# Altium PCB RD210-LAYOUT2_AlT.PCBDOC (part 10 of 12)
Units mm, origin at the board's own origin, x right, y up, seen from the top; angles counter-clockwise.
Board outline 250 x 123 mm, 4 copper layers (TOP, Mid-Layer 1, Mid-Layer 2, BOTTOM), stack 0.711 mm thick; 1043 components, 659 nets, 2786 pads, 1228 vias.
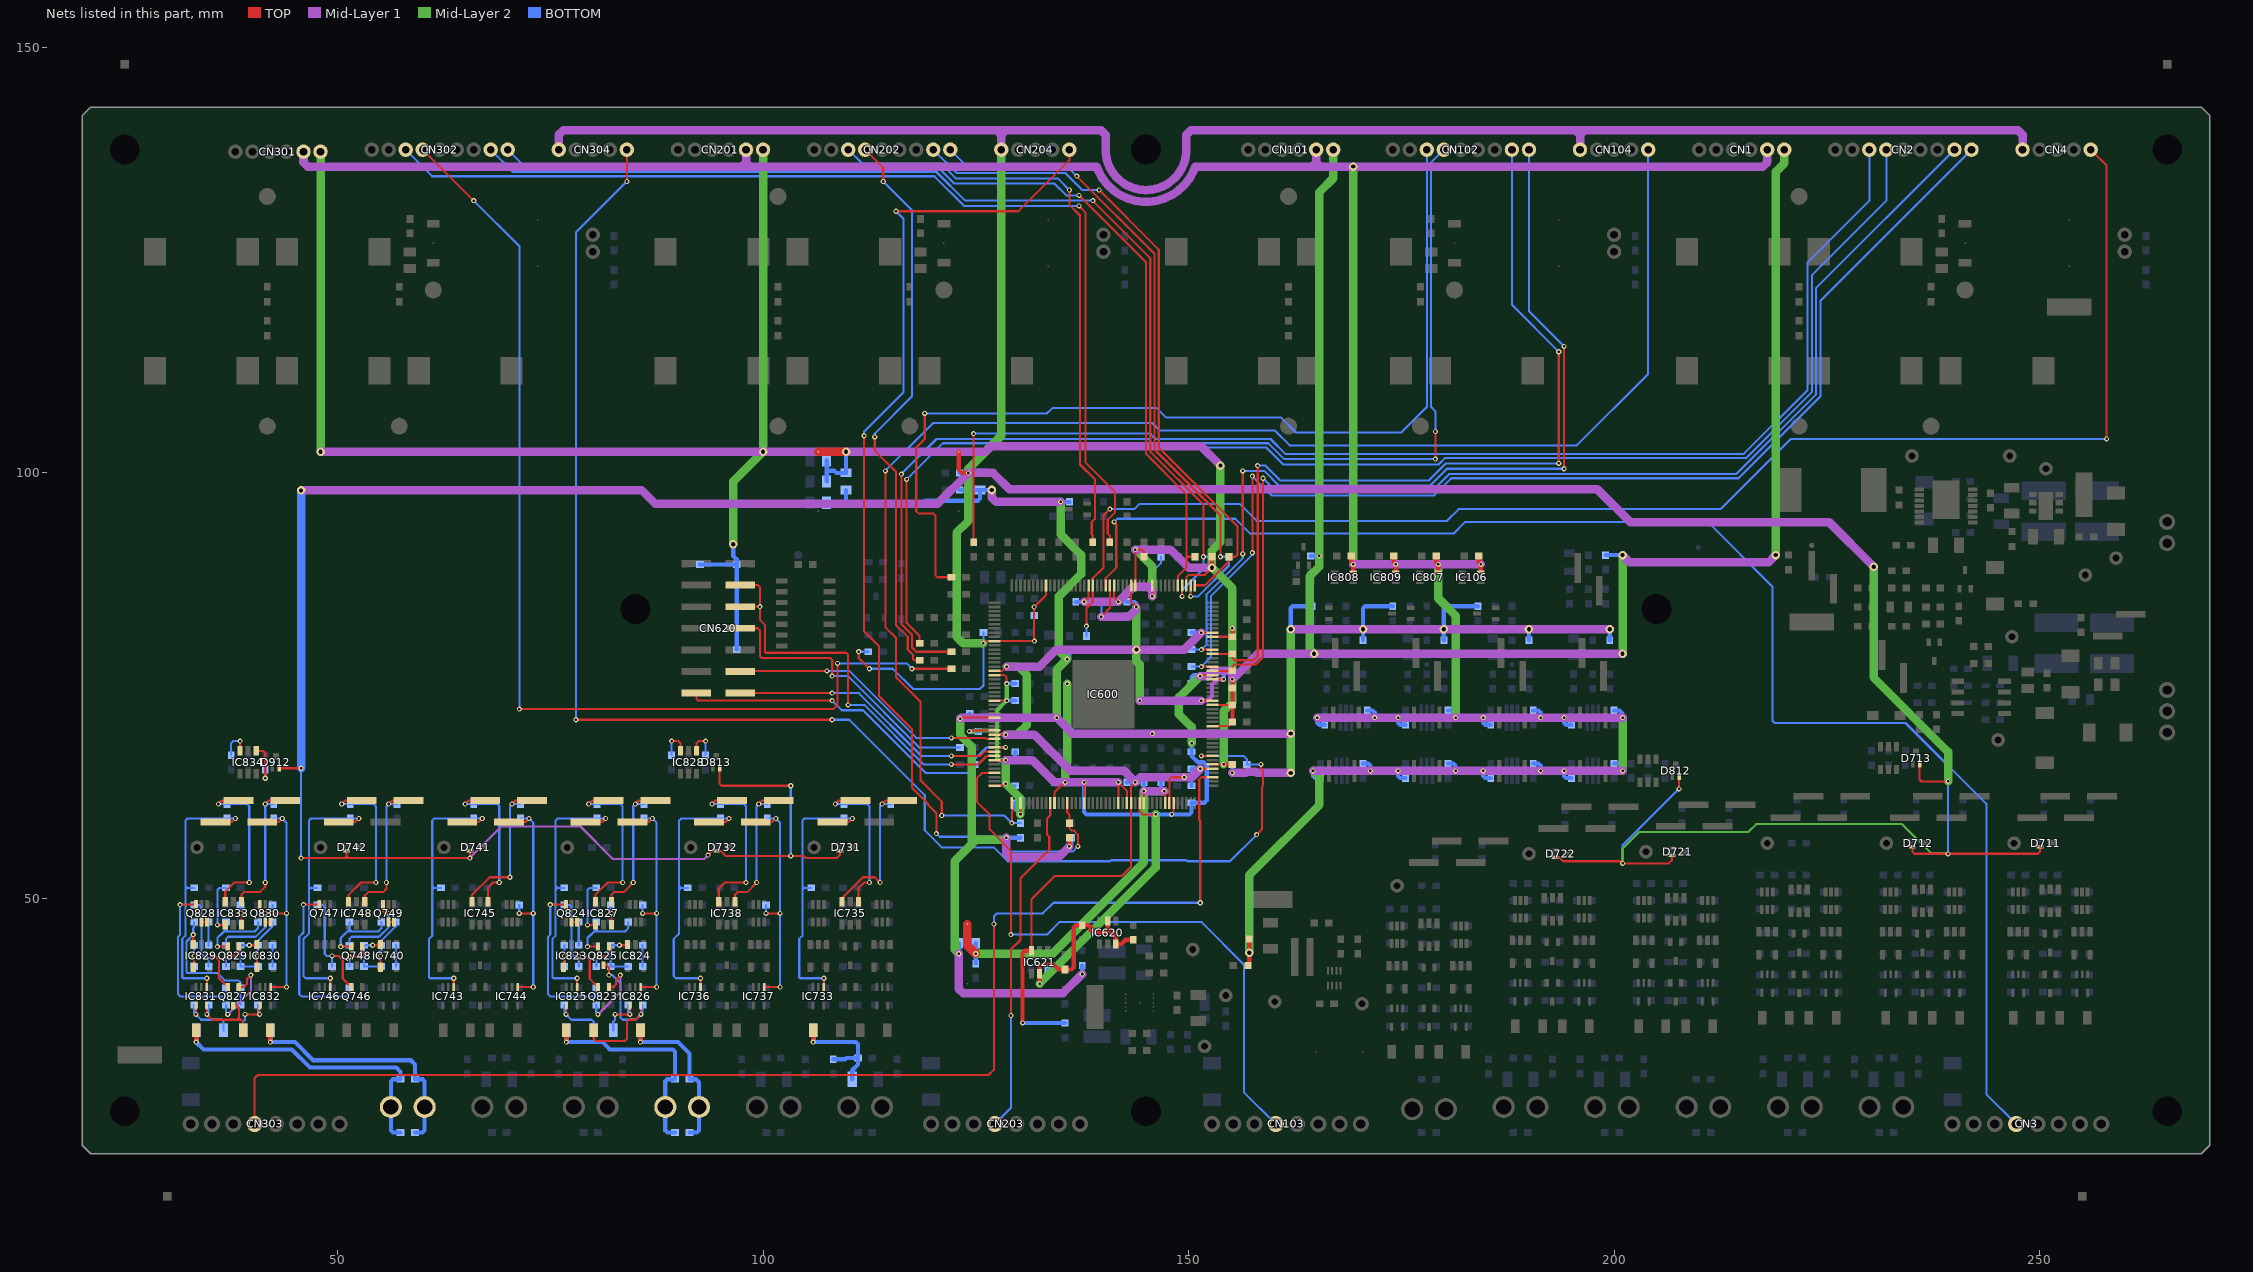
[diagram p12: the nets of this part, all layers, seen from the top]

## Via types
v1: diameter 0.6, hole 0.3, TOP to BOTTOM, 1134 vias
v2: diameter 1, hole 0.5, TOP to BOTTOM, 94 vias

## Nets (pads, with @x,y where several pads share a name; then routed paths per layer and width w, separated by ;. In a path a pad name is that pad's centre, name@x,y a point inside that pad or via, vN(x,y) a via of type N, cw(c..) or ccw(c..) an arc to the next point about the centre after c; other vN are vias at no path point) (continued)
N00400138: Q746.2 R886.1 R888.2 | length 13.7
  TOP w0.25: v1(49.35,43.25) 50.123,43.25 50.607,42.766 50.607,40.593 Q746.2@51.6,39.6
  BOTTOM w0.25: R888.2@47.65,49.25 48.25,49.25 48.5,49 48.5,43.5 48.75,43.25 v1(49.35,43.25) R886.1@49.35,42
N00400139: Q747.6 R882.2 | length 19.4
  TOP w0.25: v1(46,49.275) Q747.6@47.85,49.275
  BOTTOM w0.25: v1(46,49.275) 46,46 45.5,45.5 45.5,38.75 45.75,38.5 51.15,38.5 51.4,38.75 R882.2@51.4,39.5
N00400140: Q749.2 Q749.3 | length 0.6
  TOP w0.25: Q749.2@56,47.225 Q749.3@56.65,47.225
N00400141: Q748.1 R885.1 | length 3.6
  TOP w0.25: v1(51.4,43.147) 52.512,43.147 52.9,43.535 Q748.1@52.9,44.35
  BOTTOM w0.25: R885.1@51.4,42 v1(51.4,43.147)
N00400142: Q749.6 R883.2 | length 9.1
  TOP w0.25: Q749.6@55.35,49.275 55.35,48.5 55.6,48.25 v1(56,48.25)
  BOTTOM w0.25: R883.2@51.4,44.5 51.4,45.25 51.65,45.5 54.875,45.5 56,46.625 v1(56,48.25)
N00400144: Q748.2 R887.1 R889.2 | length 9.8
  TOP w0.25: v1(50.375,44.35) Q748.2@51.6,44.35
  BOTTOM w0.25: v1(50.375,44.35) 50.375,45.35 51.15,46.125 ; R889.2@51.4,47.25 51.4,46.375 ; R887.1@55.15,47.25 55.15,46.5 54.775,46.125 51.65,46.125 ; 51.15,46.125 51.4,46.375 ; 51.15,46.125 51.65,46.125 ; 51.4,46.375 51.65,46.125
N00400145: C781.2 IC740.3 R883.1 R885.2 | length 6.5
  TOP w0.25: v1(54.125,44.5) 54.95,44.5 IC740.3@55.05,44.6
  BOTTOM w0.25: v1(54.125,44.5) R883.1@53.1,44.5 R885.2@53.1,42 C781.2@55.15,42
N00400146: IC740.4 R881.1 R887.2 | length 6.1
  TOP w0.25: IC740.4@55.05,41.9 v1(55.05,43.25)
  BOTTOM w0.25: v1(55.05,43.25) 55.05,43.8 55.15,43.9 R881.1@55.15,44.5 55.15,45.025 56.85,46.725 R887.2@56.85,47.25
N00400149: C781.1 R881.2 | length 2.5
  BOTTOM w0.25: C781.1@56.85,42 R881.2@56.85,44.5
N00400153: C752.2 C753.2 R771.1 R773.2 R778.2 | length 15.5
  TOP w0.5: v1(105.9,33.125) R773.2@105.9,34.5
  BOTTOM w0.5: R771.1@105.9,34.5 v1(105.9,33.125) 110.9,33.125 111.15,32.875 C753.2@111.15,31.25 ; R778.2@108.25,31.1 109.625,31.1 109.775,31.25 C753.2@111.15,31.25 ; C752.2@110.475,28.75 110.475,29.825 111.15,30.5 C753.2@111.15,31.25
N00400154: C931.2 IC824.3 R963.1 R965.2 | length 6.5
  TOP w0.25: v1(83.125,44.5) 83.95,44.5 IC824.3@84.05,44.6
  BOTTOM w0.25: v1(83.125,44.5) R963.1@82.1,44.5 R965.2@82.1,42 C931.2@84.15,42
N00400155: CN929.2 IC738.1 R913.2 | length 16.8
  TOP w0.25: IC738.1@96.7,49.6 96.7,50.45 97,50.75 98.125,50.75 v1(99.25,51.875) ; v1(99.5,61.1) 99.92,61.52 CN929.2@101.85,61.52
  BOTTOM w0.25: v1(99.25,51.875) 99.25,60.85 v1(99.5,61.1) R913.2@100.5,61.1
N00400159: C944.1 IC831.5 Q827.3 R990.2 | length 10.5
  TOP w0.25: IC831.5@34.65,37.4 v1(34.65,36.375) 35.275,35.75 38.15,35.75 ; Q827.3@37.75,37.4 38.178,37.4 38.4,37.178 38.4,36 ; R990.2@38.9,34.5 38.9,35.5 38.65,35.75 ; 38.15,35.75 38.65,35.75 ; 38.15,35.75 38.4,36 ; 38.4,36 38.65,35.75
  BOTTOM w0.25: v1(34.65,36.375) 34.85,36.575 C944.1@34.85,37.5
N00400163: CN927.1 IC736.1 R713.1 R874.1 | length 32.8
  TOP w0.25: IC736.1@92.65,39.6 v1(92.65,40.625) ; CN927.1@93.65,58.98 95.58,58.98 v1(96,59.4)
  BOTTOM w0.25: R874.1@91.15,51.25 90.375,51.25 ; v1(92.65,40.625) 89.75,40.625 89.5,40.875 89.5,45.25 90.125,45.875 90.125,51 ; v1(96,59.4) R713.1@95,59.4 90.375,59.4 90.125,59.15 90.125,51.5 ; 90.125,51 90.375,51.25 ; 90.125,51 90.125,51.5 ; 90.125,51.5 90.375,51.25
N00400164: CN924.2 IC735.1 R703.2 | length 18.8
  TOP w0.25: v1(108.5,61.1) 108.92,61.52 CN924.2@110.85,61.52 ; IC735.1@111.2,49.6 111.2,51.2 111.875,51.875 v1(112.5,51.875)
  BOTTOM w0.25: v1(108.5,61.1) R703.2@109.5,61.1 112.25,61.1 112.5,60.85 v1(112.5,51.875)
N00400165: CN929.1 IC737.1 R875.1 R913.1 | length 28
  TOP w0.25: CN929.1@99.15,58.98 101.08,58.98 v1(101.5,59.4) ; IC737.1@100.15,39.6 v1(102,39.6) ; v1(100.35,48.25) v1(102,48.25)
  BOTTOM w0.25: v1(100.35,48.25) R875.1@100.35,49.25 ; R913.1@100.5,59.4 v1(101.5,59.4) 102,58.9 v1(102,48.25) v1(102,39.6)
N00400166: CN924.1 IC733.1 R703.1 R774.1 | length 32.5
  TOP w0.25: IC733.1@107.15,39.6 v1(107.15,40.625) ; CN924.1@108.15,58.98 110.08,58.98 v1(110.5,59.4)
  BOTTOM w0.25: R774.1@105.65,51.25 104.875,51.25 ; v1(107.15,40.625) 104.375,40.625 104.25,40.75 104.25,45.25 104.625,45.625 104.625,51 ; v1(110.5,59.4) R703.1@109.5,59.4 104.875,59.4 104.625,59.15 104.625,51.5 ; 104.625,51 104.875,51.25 ; 104.625,51 104.625,51.5 ; 104.625,51.5 104.875,51.25
N00400167: C930.1 R960.2 | length 2.7
  BOTTOM w0.25: R960.2@78.35,44.5 C930.1@78.35,47.25
N00400168: C935.1 IC826.5 Q825.3 R973.1 | length 21.5
  TOP w0.25: R973.1@80.1,34.5 80.1,33.5 80.35,33.25 83.75,33.25 84,33.5 84,35.5 84.25,35.75 85.025,35.75 v1(85.65,36.375) IC826.5@85.65,37.4 ; Q825.3@81.25,42.15 81.627,42.15 81.9,41.877 v1(81.9,41)
  BOTTOM w0.25: v1(81.9,41) 82.282,41 83.25,40.031 83.25,36 83.5,35.75 85.025,35.75 v1(85.65,36.375) 85.85,36.575 C935.1@85.85,37.5
N00400169: CN930.2 IC745.1 R704.2 | length 18.8
  TOP w0.25: v1(65,61.1) 65.42,61.52 CN930.2@67.35,61.52 ; IC745.1@67.7,49.6 67.7,51.315 68.26,51.875 v1(69,51.875)
  BOTTOM w0.25: v1(65,61.1) R704.2@66,61.1 68.75,61.1 69,60.85 v1(69,51.875)
N00400171: CN926.2 IC735.3 R903.2 | length 19
  TOP w0.25: IC735.3@109.3,49.6 109.3,50.05 111.75,52.5 113.125,52.5 v1(113.75,51.875) ; v1(114,61.1) 114.42,61.52 CN926.2@116.35,61.52
  BOTTOM w0.25: v1(113.75,51.875) 113.75,60.85 v1(114,61.1) R903.2@115,61.1
N00400173: IC823.4 R960.1 R966.2 | length 3.9
  TOP w0.25: IC823.4@76.55,41.9 76.65,42 v1(76.65,43.25)
  BOTTOM w0.25: R966.2@76.65,42 v1(76.65,43.25) R960.1@76.65,44.5
N00400174: Q825.2 R967.1 R969.2 | length 9.8
  TOP w0.25: v1(79.375,44.35) Q825.2@80.6,44.35
  BOTTOM w0.25: v1(79.375,44.35) 79.375,45.35 80.15,46.125 ; R969.2@80.4,47.25 80.4,46.375 ; R967.1@84.15,47.25 84.15,46.5 83.775,46.125 80.65,46.125 ; 80.15,46.125 80.4,46.375 ; 80.15,46.125 80.65,46.125 ; 80.4,46.375 80.65,46.125
N00400175: CN932.2 IC745.3 R904.2 | length 18.4
  TOP w0.25: IC745.3@65.8,49.6 65.8,50.425 67.875,52.5 v1(70.25,52.5) ; v1(70.5,61.1) 70.92,61.52 CN932.2@72.85,61.52
  BOTTOM w0.25: v1(70.25,52.5) 70.25,60.85 v1(70.5,61.1) R904.2@71.5,61.1
N00400176: IC829.4 R980.1 R986.2 | length 3.9
  TOP w0.25: IC829.4@33.05,41.9 33.15,42 v1(33.15,43.25)
  BOTTOM w0.25: R986.2@33.15,42 v1(33.15,43.25) R980.1@33.15,44.5
N00400177: CN935.2 IC748.1 R914.2 | length 17.2
  TOP w0.25: IC748.1@53.2,49.6 53.2,50.325 53.625,50.75 55.375,50.75 55.75,51.125 v1(55.75,51.875) ; v1(56,61.1) 56.42,61.52 CN935.2@58.35,61.52
  BOTTOM w0.25: v1(55.75,51.875) 55.75,60.85 v1(56,61.1) R914.2@57,61.1
N00400178: CN932.1 IC744.1 R795.1 R904.1 | length 28
  TOP w0.25: CN932.1@70.15,58.98 72.08,58.98 v1(72.5,59.4) ; IC744.1@71.15,39.6 v1(73,39.6) ; v1(71.35,48.25) v1(73,48.25)
  BOTTOM w0.25: v1(71.35,48.25) R795.1@71.35,49.25 ; R904.1@71.5,59.4 v1(72.5,59.4) 73,58.9 v1(73,48.25) v1(73,39.6)
N00400179: CN933.1 IC746.1 R714.1 R894.1 | length 32.8
  TOP w0.25: IC746.1@49.15,39.6 v1(49.15,40.625) ; CN933.1@50.15,58.98 52.08,58.98 v1(52.5,59.4)
  BOTTOM w0.25: R894.1@47.65,51.25 46.875,51.25 ; v1(49.15,40.625) 46.25,40.625 46,40.875 46,45.25 46.625,45.875 46.625,51 ; v1(52.5,59.4) R714.1@51.5,59.4 46.875,59.4 46.625,59.15 46.625,51.5 ; 46.625,51 46.625,51.5 ; 46.625,51 46.875,51.25 ; 46.625,51.5 46.875,51.25
N00400180: CN930.1 IC743.1 R704.1 R794.1 | length 32.5
  TOP w0.25: IC743.1@63.65,39.6 v1(63.65,40.625) ; CN930.1@64.65,58.98 66.58,58.98 v1(67,59.4)
  BOTTOM w0.25: R794.1@62.15,51.25 61.375,51.25 ; v1(63.65,40.625) 60.875,40.625 60.75,40.75 60.75,45.25 61.125,45.625 61.125,51 ; v1(67,59.4) R704.1@66,59.4 61.375,59.4 61.125,59.15 61.125,51.5 ; 61.125,51 61.125,51.5 ; 61.125,51 61.375,51.25 ; 61.125,51.5 61.375,51.25
N00400182: CN937.1 IC825.1 R718.1 R974.1 | length 32.5
  TOP w0.25: IC825.1@78.15,39.6 v1(78.15,40.625) ; CN937.1@79.15,58.98 81.08,58.98 v1(81.5,59.4)
  BOTTOM w0.25: R974.1@76.65,51.25 75.875,51.25 ; v1(78.15,40.625) 75.375,40.625 75.25,40.75 75.25,45.25 75.625,45.625 75.625,51 ; v1(81.5,59.4) R718.1@80.5,59.4 75.875,59.4 75.625,59.15 75.625,51.5 ; 75.625,51 75.875,51.25 ; 75.625,51 75.625,51.5 ; 75.625,51.5 75.875,51.25
N00400183: C941.2 IC830.3 R983.1 R985.2 | length 6.5
  TOP w0.25: v1(39.625,44.5) 40.45,44.5 IC830.3@40.55,44.6
  BOTTOM w0.25: v1(39.625,44.5) R983.1@38.6,44.5 R985.2@38.6,42 C941.2@40.65,42
N00400184: C945.2 IC832.4 R992.2 | length 5.9
  TOP w0.25: v1(39.125,36.375) v1(40.85,36.375) IC832.4@40.85,37.4
  BOTTOM w0.25: R992.2@38.9,34.5 38.9,35.525 39.125,35.75 v1(39.125,36.375) ; C945.2@40.65,37.5 40.65,36.575 v1(40.85,36.375)
N00400185: CN939.2 IC827.1 R918.2 | length 16.8
  TOP w0.25: IC827.1@82.2,49.6 82.2,50.45 82.5,50.75 83.625,50.75 v1(84.75,51.875) ; v1(85,61.1) 85.42,61.52 CN939.2@87.35,61.52
  BOTTOM w0.25: v1(84.75,51.875) 84.75,60.85 v1(85,61.1) R918.2@86,61.1
N00400186: CN937.2 IC827.3 R718.2 | length 20.2
  TOP w0.25: v1(79.5,61.1) 79.92,61.52 CN937.2@81.85,61.52 ; IC827.3@80.3,49.6 80.3,50.425 81.75,51.875 v1(83.5,51.875)
  BOTTOM w0.25: v1(79.5,61.1) R718.2@80.5,61.1 83.25,61.1 83.5,60.85 v1(83.5,51.875)
N00400187: IC833.6 R996.1 | length 2.4
  TOP w0.25: IC833.6@38.7,46.9 v1(38.7,48.25)
  BOTTOM w0.25: R996.1@38.6,49.25 38.6,48.725 38.7,48.625 v1(38.7,48.25)
N00400191: CN943.1 IC832.1 R919.1 R995.1 | length 28
  TOP w0.25: CN943.1@41.15,58.98 43.08,58.98 v1(43.5,59.4) ; IC832.1@42.15,39.6 v1(44,39.6) ; v1(42.35,48.25) v1(44,48.25)
  BOTTOM w0.25: v1(42.35,48.25) R995.1@42.35,49.25 ; R919.1@42.5,59.4 v1(43.5,59.4) 44,58.9 v1(44,48.25) v1(44,39.6)
N00400192: C935.2 IC826.4 R972.2 | length 5.9
  TOP w0.25: v1(82.625,36.375) v1(84.35,36.375) IC826.4@84.35,37.4
  BOTTOM w0.25: R972.2@82.4,34.5 82.4,35.525 82.625,35.75 v1(82.625,36.375) ; C935.2@84.15,37.5 84.15,36.575 v1(84.35,36.375)
N00400193: CN939.1 IC826.1 R918.1 R975.1 | length 28
  TOP w0.25: CN939.1@84.65,58.98 86.58,58.98 v1(87,59.4) ; IC826.1@85.65,39.6 v1(87.5,39.6) ; v1(85.85,48.25) v1(87.5,48.25)
  BOTTOM w0.25: v1(85.85,48.25) R975.1@85.85,49.25 ; R918.1@86,59.4 v1(87,59.4) 87.5,58.9 v1(87.5,48.25) v1(87.5,39.6)
N00400194: C933.1 CN936.1 R970.1 R972.1 R979.2 | length 20.2
  TOP w0.5: v1(85.6,33.125) R970.1@85.6,34.5
  BOTTOM w0.5: R972.1@85.6,34.5 v1(85.6,33.125) 90,33.125 91.35,31.775 R979.2@91.35,28.75 92.125,28.75 92.48,28.395 92.48,22.75 92.23,22.5 C933.1@91.35,22.5
N00400202: C933.2 CN936.2 R971.1 R973.2 R979.1 | length 27.4
  TOP w0.5: v1(76.9,33.125) R973.2@76.9,34.5
  BOTTOM w0.5: R971.1@76.9,34.5 v1(76.9,33.125) 81.125,33.125 82,32.25 89.4,32.25 89.65,32 R979.1@89.65,28.75 88.75,28.75 88.52,28.52 CN936.2@88.52,25.5 88.52,22.75 88.77,22.5 C933.2@89.65,22.5
N00400204: C934.2 IC825.4 R971.2 | length 6.8
  TOP w0.25: v1(76.85,36.375) IC825.4@76.85,37.4
  BOTTOM w0.25: C934.2@76.65,37.5 76.65,36.575 v1(76.85,36.375) 77.475,35.75 79.85,35.75 80.1,35.5 R971.2@80.1,34.5
N00400205: Q830.6 R983.2 | length 9.1
  TOP w0.25: Q830.6@40.85,49.275 40.85,48.5 41.1,48.25 v1(41.5,48.25)
  BOTTOM w0.25: R983.2@36.9,44.5 36.9,45.25 37.15,45.5 40.375,45.5 41.5,46.625 v1(41.5,48.25)
N00400206: Q830.2 Q830.3 | length 0.6
  TOP w0.25: Q830.2@41.5,47.225 Q830.3@42.15,47.225
N00400208: IC827.6 R976.1 | length 2.4
  TOP w0.25: IC827.6@82.2,46.9 v1(82.2,48.25)
  BOTTOM w0.25: R976.1@82.1,49.25 82.1,48.725 82.2,48.625 v1(82.2,48.25)
N00400211: C940.1 R980.2 | length 2.7
  BOTTOM w0.25: R980.2@34.85,44.5 C940.1@34.85,47.25
N00400212: Q827.2 R986.1 R988.2 | length 13.7
  TOP w0.25: v1(34.85,43.25) 35.59,43.25 36.074,42.766 36.074,40.625 Q827.2@37.1,39.6
  BOTTOM w0.25: R988.2@33.15,49.25 33.75,49.25 34,49 34,43.5 34.25,43.25 v1(34.85,43.25) R986.1@34.85,42
N00400213: C940.2 IC829.3 R982.1 R984.2 | length 16.9
  TOP w0.25: IC829.3@33.05,44.6 v1(33.05,45.75)
  BOTTOM w0.25: C940.2@33.15,47.25 33.15,46.6 33.05,46.5 v1(33.05,45.75) 32.25,44.95 32.25,41.375 32.375,41.25 35.875,41.25 36.75,40.375 38.35,40.375 38.6,40.125 R982.1@38.6,39.5 R984.2@38.6,37.5
N00400214: C943.2 CN940.2 R991.1 R993.2 R999.1 | length 37.3
  TOP w0.5: v1(33.4,33.125) R993.2@33.4,34.5
  BOTTOM w0.5: R991.1@33.4,34.5 v1(33.4,33.125) 33.4,33.1 34.25,32.25 44.625,32.25 46.75,30.125 56.9,30.125 57.4,29.625 R999.1@57.4,28.75 56.52,28.75 56.27,28.5 CN940.2@56.27,25.5 56.27,22.75 56.52,22.5 C943.2@57.4,22.5
N00400216: Q828.2 Q828.3 | length 0.7
  TOP w0.25: Q828.2@34,47.225 Q828.3@34.65,47.225
N00400217: Q827.1 R984.1 | length 9.3
  TOP w0.25: Q827.1@38.4,39.6 38.987,39.6 39.359,39.972 39.359,40.543 v1(39.812,40.997)
  Mid-Layer 1 w0.25: v1(37.1,36.375) 39.812,39.087 v1(39.812,40.997)
  BOTTOM w0.25: R984.1@36.9,37.5 36.9,36.575 v1(37.1,36.375)
N00400220: Q828.6 R982.2 | length 19.1
  TOP w0.25: v1(31.5,49.275) Q828.6@33.35,49.275
  BOTTOM w0.25: v1(31.5,49.275) 31.5,45.75 31.25,45.5 31.25,38.75 31.5,38.5 36.65,38.5 36.9,38.75 R982.2@36.9,39.5
N00400221: CN941.2 IC833.3 R719.2 | length 19.7
  TOP w0.25: v1(36,61.1) 36.42,61.52 CN941.2@38.35,61.52 ; IC833.3@36.8,49.6 36.8,50.8 37.875,51.875 v1(39.625,51.875)
  BOTTOM w0.25: v1(36,61.1) R719.2@37,61.1 39.375,61.1 39.625,60.85 v1(39.625,51.875)
N00400224: IC833.4 R997.1 | length 6.2
  TOP w0.25: v1(35.875,46.9) IC833.4@36.8,46.9
  BOTTOM w0.25: v1(35.875,46.9) 35.875,51 36.125,51.25 R997.1@36.9,51.25
N00400225: CN943.2 IC833.1 R919.2 | length 17.3
  TOP w0.25: IC833.1@38.7,49.6 38.7,50.45 39,50.75 40.875,50.75 41.5,51.375 v1(41.5,51.875) ; v1(41.5,61.1) 41.92,61.52 CN943.2@43.85,61.52
  BOTTOM w0.25: v1(41.5,51.875) v1(41.5,61.1) R919.2@42.5,61.1
N00400226: IC827.4 R977.1 | length 6.2
  TOP w0.25: v1(79.375,46.9) IC827.4@80.3,46.9
  BOTTOM w0.25: v1(79.375,46.9) 79.375,51 79.625,51.25 R977.1@80.4,51.25
N00400228: IC834.6 R709.1 | length 3.7
  TOP w0.25: IC834.6@38.55,67.35 v1(38.55,68.5)
  BOTTOM w0.25: R709.1@37.5,66.85 37.5,68.25 37.75,68.5 v1(38.55,68.5)
N00400229: Q829.1 R985.1 | length 3.7
  TOP w0.25: v1(36.9,43.274) 38.098,43.274 38.4,43.576 Q829.1@38.4,44.35
  BOTTOM w0.25: R985.1@36.9,42 v1(36.9,43.274)
N00400230: Q829.2 R987.1 R989.2 | length 9.8
  TOP w0.25: v1(35.875,44.35) Q829.2@37.1,44.35
  BOTTOM w0.25: v1(35.875,44.35) 35.875,45.35 36.65,46.125 ; R989.2@36.9,47.25 36.9,46.375 ; R987.1@40.65,47.25 40.65,46.5 40.275,46.125 37.15,46.125 ; 36.65,46.125 36.9,46.375 ; 36.65,46.125 37.15,46.125 ; 36.9,46.375 37.15,46.125
N00400231: IC834.4 R909.1 | length 5.2
  TOP w0.25: IC834.4@40.45,67.35 41.25,67.35 41.5,67.1 v1(41.5,64.125)
  BOTTOM w0.25: v1(41.5,64.125) R909.1@41.5,65.15
N00400232: IC830.4 R981.1 R987.2 | length 6.1
  TOP w0.25: IC830.4@40.55,41.9 v1(40.55,43.25)
  BOTTOM w0.25: v1(40.55,43.25) 40.55,43.8 40.65,43.9 R981.1@40.65,44.5 40.65,45.025 42.35,46.725 R987.2@42.35,47.25
N00400233: C941.1 R981.2 | length 2.5
  BOTTOM w0.25: C941.1@42.35,42 R981.2@42.35,44.5
N00400234: Q823.1 R964.1 | length 9.2
  TOP w0.25: Q823.1@81.9,39.6 82.421,39.6 82.738,39.917 82.738,40.48 v1(83.246,40.988)
  Mid-Layer 1 w0.25: v1(80.6,36.375) 83.246,39.021 v1(83.246,40.988)
  BOTTOM w0.25: R964.1@80.4,37.5 80.4,36.575 v1(80.6,36.375)
N00400235: Q823.2 R966.1 R968.2 | length 13.7
  TOP w0.25: v1(78.35,43.25) 79.151,43.25 79.635,42.766 79.635,40.565 Q823.2@80.6,39.6
  BOTTOM w0.25: R968.2@76.65,49.25 77.25,49.25 77.5,49 77.5,43.5 77.75,43.25 v1(78.35,43.25) R966.1@78.35,42
N00400236: Q824.6 R962.2 | length 19.1
  TOP w0.25: v1(75,49.275) Q824.6@76.85,49.275
  BOTTOM w0.25: v1(75,49.275) 75,45.75 74.75,45.5 74.75,38.75 75,38.5 80.15,38.5 80.4,38.75 R962.2@80.4,39.5
N00400237: C931.1 R961.2 | length 2.5
  BOTTOM w0.25: C931.1@85.85,42 R961.2@85.85,44.5
N00400239: Q824.2 Q824.3 | length 0.6
  TOP w0.25: Q824.2@77.5,47.225 Q824.3@78.15,47.225
N00400242: Q825.1 R965.1 | length 3.7
  TOP w0.25: v1(80.4,43.21) 81.595,43.21 81.9,43.515 Q825.1@81.9,44.35
  BOTTOM w0.25: R965.1@80.4,42 v1(80.4,43.21)
N00400243: CN941.1 IC831.1 R719.1 R994.1 | length 32.5
  TOP w0.25: IC831.1@34.65,39.6 v1(34.65,40.625) ; CN941.1@35.65,58.98 37.58,58.98 v1(38,59.4)
  BOTTOM w0.25: R994.1@33.15,51.25 32.375,51.25 ; v1(34.65,40.625) 31.875,40.625 31.75,40.75 31.75,45.25 32.125,45.625 32.125,51 ; v1(38,59.4) R719.1@37,59.4 32.375,59.4 32.125,59.15 32.125,51.5 ; 32.125,51 32.125,51.5 ; 32.125,51 32.375,51.25 ; 32.125,51.5 32.375,51.25
N00400244: C944.2 IC831.4 R991.2 | length 6.8
  TOP w0.25: v1(33.35,36.375) IC831.4@33.35,37.4
  BOTTOM w0.25: C944.2@33.15,37.5 33.15,36.575 v1(33.35,36.375) 33.975,35.75 36.35,35.75 36.6,35.5 R991.2@36.6,34.5
N00400246: CN927.2 IC738.3 R713.2 | length 20.7
  TOP w0.25: v1(94,61.1) 94.42,61.52 CN927.2@96.35,61.52 ; IC738.3@94.8,49.6 94.8,51.175 95.5,51.875 v1(98,51.875)
  BOTTOM w0.25: v1(94,61.1) R713.2@95,61.1 97.75,61.1 98,60.85 v1(98,51.875)
N00400247: C943.1 CN940.1 R990.1 R992.1 R999.2 | length 30.8
  TOP w0.5: v1(42.1,33.125) R990.1@42.1,34.5
  BOTTOM w0.5: R992.1@42.1,34.5 v1(42.1,33.125) 45,33.125 47.125,31 58.6,31 59.1,30.5 R999.2@59.1,28.75 59.98,28.75 60.23,28.5 60.23,22.75 59.98,22.5 C943.1@59.1,22.5
N00400253: IC828.6 R708.1 | length 3.7
  TOP w0.25: v1(89.25,68.5) 90.05,68.5 90.3,68.25 IC828.6@90.3,67.35
  BOTTOM w0.25: R708.1@89.25,66.85 v1(89.25,68.5)
N00400256: IC828.4 R908.1 | length 3.7
  TOP w0.25: IC828.4@92.2,67.35 92.2,68.25 92.45,68.5 v1(93.25,68.5)
  BOTTOM w0.25: R908.1@93.25,66.85 v1(93.25,68.5)
N00400257: CN933.2 IC748.3 R714.2 | length 20.2
  TOP w0.25: v1(50.5,61.1) 50.92,61.52 CN933.2@52.85,61.52 ; IC748.3@51.3,49.6 51.3,50.425 52.75,51.875 v1(54.5,51.875)
  BOTTOM w0.25: v1(50.5,61.1) R714.2@51.5,61.1 54.25,61.1 54.5,60.85 v1(54.5,51.875)
PowrGood_0-1: CN4.1 IC600.25 R514.2 | length 173
  TOP w0.25: v1(138,82) 138,84.125 138.75,84.875 IC600.25@138.75,86.8 138.75,87.625 140,88.875 140,95 v1(140.75,95.75) ; CN4.1@256,138 257.875,136.125 v1(257.875,104)
  BOTTOM w0.25: R514.2@138,80.85 v1(138,82) ; v1(140.75,95.75) 143.625,95.75 144.25,96.375 156,96.375 158,94.375 180.375,94.375 181.75,95.75 212.5,95.75 220.75,104 v1(257.875,104)
PowrGood_0-2: CN104.1 IC600.89 R524.1 | length 178.1
  TOP w0.25: v1(114.375,100.25) 114.375,81.875 115.625,80.625 115.625,76 118.5,73.125 118.5,63.875 121,61.375 v1(121,59.75) ; v1(129.25,58.85) IC600.89@129.25,61.2
  BOTTOM w0.25: v1(114.375,100.25) 120,105.875 145.75,105.875 146.625,105 160.125,105 161.875,103.25 195.625,103.25 204,111.625 CN104.1@204,138 ; v1(121,59.75) 128.35,59.75 v1(129.25,58.85) R524.1@130.25,58.85
PowrGood_0-3: CN204.1 IC600.102 R534.1 | length 126.5
  TOP w0.25: v1(111.875,104.375) 111.875,81.375 113.625,79.625 113.625,73.75 117.5,69.875 117.5,63 119.375,61.125 119.375,61 120.375,60 v1(120.375,57.625) ; v1(115.625,130.75) 130,130.75 136,136.75 CN204.1@136,138 ; IC600.102@135.75,61.2 135.75,60.125 136,59.875 R534.1@136,58.85 136,58.25 136.25,58 136.5,58 137,57.5 v1(137,56.125)
  BOTTOM w0.25: v1(111.875,104.375) 111.875,104.875 116.5,109.5 116.5,129.875 v1(115.625,130.75) ; v1(120.375,57.625) 120.75,57.25 127.375,57.25 129.125,55.5 136.375,55.5 v1(137,56.125)
PowrGood_0-4: CN304.1 IC600.140 R544.2 | length 177.9
  TOP w0.25: v1(78,71) v1(108.125,71) ; v1(84,134.25) CN304.1@84,138 ; v1(151.5,66.75) IC600.140@152.8,66.75 ; v1(158,57.5) 158.625,58.125 158.625,63.125 158.75,63.25 158.75,65 158.5,65.25 v1(158.5,65.75)
  BOTTOM w0.25: v1(78,71) 78,128.25 v1(84,134.25) ; v1(108.125,71) 110.125,71 119,62.125 119,58 121,56 127.125,56 128.75,54.375 140.75,54.375 140.875,54.5 149.75,54.5 149.875,54.375 154.875,54.375 v1(158,57.5) ; v1(151.5,66.75) 156.475,66.75 156.85,66.375 R544.2@156.85,65.75 v1(158.5,65.75)
PWM_H_0-1: CN2.2 IC600.160 R551.2 | length 133.7
  TOP w0.25: IC600.160@152.8,76.75 R551.2@155.15,76.75 155.15,77.25 155.4,77.5 157.875,77.5 158.75,78.375 v1(158.75,99.375)
  BOTTOM w0.25: v1(158.75,99.375) 160.25,97.875 178.625,97.875 180.625,99.875 214.375,99.875 223.75,109.25 223.75,121.75 CN2.2@240,138
PWM_H_0-2: CN102.2 IC600.164 R552.2 | length 104.6
  TOP w0.25: IC600.164@152.8,78.75 R552.2@155.15,78.75 155.15,78.25 155.4,78 157.625,78 158.125,78.5 v1(158.125,100.875) ; v1(193.5,101.125) v1(193.5,114.25)
  BOTTOM w0.25: v1(158.125,100.875) 159,100.875 160.75,99.125 178.25,99.125 180.25,101.125 v1(193.5,101.125) ; CN102.2@188,138 188,119.75 v1(193.5,114.25)
PWM_H_0-3: CN202.2 IC600.1 R553.2 | length 77.8
  TOP w0.25: v1(139.5,133.25) 146.5,126.25 146.5,103 155.75,93.75 155.75,90.4 155.5,90.15 R553.2@154.75,90.15 154.75,89.625 151.925,86.8 IC600.1@150.75,86.8
  BOTTOM w0.25: CN202.2@120,138 122.75,135.25 135.5,135.25 137.5,133.25 v1(139.5,133.25)
PWM_H_0-4: CN302.2 IC600.4 R554.2 | length 128.5
  TOP w0.25: v1(138.75,132) 145.5,125.25 145.5,102.5 151.75,96.25 v1(151.75,90.15) ; v1(149.25,85.5) IC600.4@149.25,86.8
  BOTTOM w0.25: CN302.2@68,138 70.625,135.375 120.375,135.375 123.75,132 v1(138.75,132) ; v1(149.25,85.5) 149.25,86.25 151.75,88.75 v1(151.75,90.15) R554.2@152.75,90.15
PWM_L_0-1: CN2.1 IC600.161 R556.2 | length 136.2
  TOP w0.25: v1(151.5,77.25) IC600.161@152.8,77.25 ; v1(157.5,90.625) v1(157.5,99.625)
  BOTTOM w0.25: R556.2@150.35,77.25 v1(151.5,77.25) 152.625,78.375 152.625,85.5 157.5,90.375 v1(157.5,90.625) ; v1(157.5,99.625) 159.75,97.375 178.875,97.375 180.875,99.375 214.625,99.375 224.25,109 224.25,120.25 CN2.1@242,138
PWM_L_0-2: CN102.1 IC600.165 R557.2 | length 104
  TOP w0.25: v1(151.5,79.25) IC600.165@152.8,79.25 ; v1(156.375,90.5) v1(156.375,100.25) ; v1(194.125,100.5) v1(194.125,114.875)
  BOTTOM w0.25: R557.2@150.35,79.25 v1(151.5,79.25) 152.125,79.875 152.125,85.75 156.375,90 v1(156.375,90.5) ; v1(156.375,100.25) 158.875,100.25 160.625,98.5 178.375,98.5 180.375,100.5 v1(194.125,100.5) ; CN102.1@190,138 190,119 v1(194.125,114.875)
PWM_L_0-3: CN202.1 IC600.2 R558.2 | length 77.2
  TOP w0.25: v1(136.875,134.875) 146,125.75 146,102.75 153.75,95 v1(153.75,90.15) ; v1(150.25,85.5) IC600.2@150.25,86.8
  BOTTOM w0.25: CN202.1@122,138 124.125,135.875 135.875,135.875 v1(136.875,134.875) ; v1(150.25,85.5) 151.125,85.5 154.75,89.125 R558.2@154.75,90.15 v1(153.75,90.15)
PWM_L_0-4: CN302.1 IC600.5 R559.2 | length 122.3
  TOP w0.25: v1(137.125,132.625) 145,124.75 145,102.25 149.75,97.5 149.75,90.4 ; IC600.5@148.75,86.8 148.75,87.875 149.75,88.875 149.75,89.9 ; R559.2@150.75,90.15 150,90.15 ; 149.75,89.9 150,90.15 ; 149.75,89.9 149.75,90.4 ; 149.75,90.4 150,90.15
  BOTTOM w0.25: CN302.1@70,138 72.125,135.875 120.625,135.875 122.5,134 134.25,134 135.625,132.625 v1(137.125,132.625)
STBY_0-1: CN3.5 IC600.22 | length 174
  TOP w0.25: IC600.22@140.25,86.8 140.25,87.625 141.5,88.875 141.5,94 v1(141.25,94.25)
  BOTTOM w0.25: v1(141.25,94.25) 141.625,94.625 155.5,94.625 157.25,92.875 181.125,92.875 182.5,94.25 211,94.25 218.625,86.625 218.625,70.875 218.875,70.625 234.25,70.625 243.75,61.125 243.75,27 CN3.5@247.25,23.5
STBY_0-2: CN103.5 IC600.85 | length 72.7
  TOP w0.25: IC600.85@127.2,64.75 125.75,64.75 125.125,64.125 125.125,61.375 126.625,59.875 126.625,58.125 129.125,55.625 v1(129.125,45.75)
  BOTTOM w0.25: v1(129.125,45.75) 133.375,45.75 134.875,47.25 151.5,47.25 156.5,42.25 156.5,27.25 CN103.5@160.25,23.5
STBY_0-3: CN203.5 IC600.98 | length 40.6
  TOP w0.25: v1(129.125,36.25) 129.125,44 130.25,45.125 130.25,52.375 133.625,55.75 133.625,57.25 133.375,57.5 133.375,59.375 133.75,59.75 IC600.98@133.75,61.2
  BOTTOM w0.25: CN203.5@127.25,23.5 129.125,25.375 v1(129.125,36.25)
STBY_0-4: CN303.5 IC600.135 | length 151.8
  TOP w0.25: CN303.5@40.25,23.5 40.25,28.875 40.625,29.25 126.5,29.25 127.125,29.875 v1(127.125,47) ; v1(151.375,49.5) 151.375,59.125 151.25,59.25 151.25,64 151.5,64.25 IC600.135@152.8,64.25
  BOTTOM w0.25: v1(127.125,47) 127.125,47.875 127.5,48.25 132.875,48.25 134.125,49.5 v1(151.375,49.5)
TCK: CN620.9 CN620.11 IC600.81 | length 48.8
  TOP w0.25: CN620.9@97.34,84.29 v1(99.625,84.29) ; CN620.11@97.34,86.83 99.375,86.83 99.625,86.58 v1(99.625,84.29) ; v1(110,72.75) 110,78.625 109.75,78.875 100.375,78.875 100.25,79 100.25,82.125 99.625,82.75 v1(99.625,84.29) ; v1(122.125,65.75) 125.25,65.75 126.25,66.75 IC600.81@127.2,66.75
  BOTTOM w0.25: v1(110,72.75) 111.875,72.75 118.875,65.75 v1(122.125,65.75)
TDI: CN620.3 IC600.77 | length 33.2
  TOP w0.25: CN620.3@97.34,76.67 97.42,76.75 v1(107.5,76.75) ; v1(122.125,68.875) 126.125,68.875 126.25,68.75 IC600.77@127.2,68.75
  BOTTOM w0.25: v1(107.5,76.75) 110.125,76.75 118,68.875 v1(122.125,68.875)
TDO: CN620.7 R659.2 | length 34.5
  TOP w0.25: CN620.7@97.34,81.75 99.375,81.75 99.625,81.5 99.625,78.5 99.875,78.25 107.875,78.25 108.125,78 v1(108.125,76.125)
  BOTTOM w0.25: v1(108.125,76.125) 110,76.125 118.375,67.75 R659.2@123.15,67.75
TMS: CN620.1 IC600.80 | length 33.1
  TOP w0.25: CN620.1@97.34,74.13 v1(108.125,74.13) ; v1(122.125,66.75) 125.5,66.75 126,67.25 IC600.80@127.2,67.25
  BOTTOM w0.25: v1(108.125,74.13) 111.245,74.13 118.625,66.75 v1(122.125,66.75)
TRST_N: CN620.2 IC600.79 R669.2 | length 43.9
  TOP w0.25: CN620.2@92.16,74.13 92.16,73.5 92.41,73.25 v1(108.125,73.25) ; IC600.79@127.2,67.75 v1(128.5,67.75)
  BOTTOM w0.25: v1(108.125,73.25) 109.25,72.125 111.75,72.125 119.125,64.75 124.6,64.75 124.85,65 R669.2@124.85,65.75 124.85,66.35 126.25,67.75 v1(128.5,67.75)
V_B0-1: CN2.7 R512.2 | length 146.1
  TOP w0.25: R512.2@124.75,91.85 v1(124.75,104.625)
  BOTTOM w0.25: v1(124.75,104.625) 145.5,104.625 146.125,104 159.625,104 161.375,102.25 215.25,102.25 222.75,109.75 222.75,124.75 230,132 CN2.7@230,138
V_B0-2: CN102.7 R522.1 | length 115.3
  TOP w0.25: v1(119,107) 119,104 118,103 118,95.5 118.25,95.25 120,95.25 120.25,95 120.25,88 120.5,87.75 R522.1@122.15,87.75
  BOTTOM w0.25: v1(119,107) 133.375,107 134,107.625 146.25,107.625 147.375,106.5 160.875,106.5 162.625,104.75 175,104.75 178,107.75 CN102.7@178,138
V_B0-3: CN202.7 R532.1 | length 70.8
  TOP w0.25: v1(136,133.25) 136,131.5 137.25,130.25 137.25,101 139,99.25 139,94.625 138.625,94.25 138.625,92.75 138.75,92.625 R532.1@138.75,91.85
  BOTTOM w0.25: CN202.7@110,138 111.625,136.375 120.875,136.375 122.625,134.625 134.625,134.625 v1(136,133.25)
V_B0-4: CN302.7 R542.1 | length 123.6
  TOP w0.25: v1(137.125,131.375) 137.875,130.625 137.875,101.25 141.375,97.75 141.375,95.375 140.5,94.5 140.5,92.875 140.75,92.625 R542.1@140.75,91.85
  BOTTOM w0.25: CN302.7@58,138 61.125,134.875 120.125,134.875 123.625,131.375 v1(137.125,131.375)
V_C0-1: CN2.6 R513.1 | length 164.7
  TOP w0.25: v1(116.875,99.25) 116.875,82.375 118.4,80.85 R513.1@118.4,80
  BOTTOM w0.25: v1(116.875,99.25) 121.125,103.5 145,103.5 145.5,103 159.125,103 161.125,101 179.375,101 180.125,101.75 215.5,101.75 223.25,109.5 223.25,123.25 232,132 CN2.6@232,138
V_C0-2: CN102.6 R523.1 | length 128.4
  TOP w0.25: v1(116.25,99.875) 116.25,82.25 117.5,81 117.5,79.5 118,79 R523.1@122.15,79 ; v1(179,101.625) v1(179,104.875)
  BOTTOM w0.25: v1(116.25,99.875) 120.375,104 145.25,104 145.75,103.5 159.375,103.5 161.25,101.625 v1(179,101.625) ; v1(179,104.875) 179,107.25 178.5,107.75 178.5,136.5 CN102.6@180,138
V_C0-3: CN202.6 R533.1 | length 66.7
  TOP w0.25: CN202.6@112,138 114.125,135.875 v1(114.125,134.25) ; v1(113.125,104.25) 113.125,102.625 115.625,100.125 115.625,82.125 117,80.75 117,79.25 117.625,78.625 117.625,78.125 117.75,78 R533.1@118.4,78
  BOTTOM w0.25: v1(113.125,104.25) 113.125,104.625 117.5,109 117.5,130.875 v1(114.125,134.25)
V_C0-4: CN302.6 R543.1 | length 126.6
  TOP w0.25: CN302.6@60,138 v1(66,132) ; v1(71.375,72.25) 108.265,72.25 108.75,72.735 v1(108.75,77.625) ; v1(117.5,77) R543.1@122.15,77
  BOTTOM w0.25: v1(66,132) 71.375,126.625 v1(71.375,72.25) ; v1(108.75,77.625) 116.875,77.625 v1(117.5,77)
VDD: C665.2 C666.2 C667.1 C668.1 C669.1 C670.1 C671.2 C672.2 C673.2 C674.2 IC600.16 IC600.21 IC600.61 IC600.76 IC600.117 IC600.126 IC600.137 IC600.153 IC600.158 IC600.169 IC621.3 J804.2 | length 168.7
  TOP w0.25: IC600.76@127.2,69.25 v1(128.5,69.25) ; IC600.61@127.2,76.75 128.125,76.75 v1(128.625,77.25) ; IC621.3@131.55,43.85 131.55,49.925 134.25,52.625 142.125,52.625 143.25,53.75 IC600.117@143.25,61.2 143.25,63.15 v1(143.75,63.65) ; v1(139.75,83.125) 140.75,84.125 IC600.21@140.75,86.8 ; IC600.16@143.25,86.8 143.25,84.875 v1(143.875,84.25) ; IC600.126@147.75,61.2 147.75,64 148,64.25 v1(149.5,64.25) ; v1(151.375,65.25) IC600.137@152.8,65.25 ; v1(151.5,73.25) IC600.153@152.8,73.25 ; v1(151.5,81.25) IC600.169@152.8,81.25 ; IC600.158@152.8,75.75 v1(154.125,75.75)
  TOP w0.5: v1(130.5,35.375) 130.5,43.6 130.75,43.85 IC621.3@131.55,43.85
  Mid-Layer 1 w0.5: v1(151.5,73.25) 152.25,73.25 152.75,73.75 152.75,75.125 153.375,75.75 v1(154.125,75.75)
  Mid-Layer 1 w1: v1(128.5,69.25) 131.875,69.25 136.125,65 142.4,65 v1(143.75,63.65) 144.35,64.25 v1(149.5,64.25) 150.375,64.25 v1(151.375,65.25) ; v1(128.625,77.25) 132.5,77.25 134.5,79.25 v2(143.875,79.25) 149.5,79.25 v1(151.5,81.25) ; v1(139.75,83.125) 143,83.125 143.875,84 v1(143.875,84.25) ; v1(144.25,73.25) v1(151.5,73.25)
  Mid-Layer 2 w1: v1(128.5,69.25) 129.875,69.25 131,70.375 131,76.25 130,77.25 v1(128.625,77.25) ; v1(143.875,84.25) v2(143.875,79.25) 143.875,77.875 144.25,77.5 v1(144.25,73.25)
  BOTTOM w0.25: C666.2@138.75,84.85 139.525,84.85 139.75,84.625 v1(139.75,83.125)
  BOTTOM w0.5: v1(128.5,69.25) C668.1@129.65,69.25 ; v1(128.625,77.25) C667.1@129.65,77.25 ; v1(130.5,35.375) J804.2@135.5,35.375 ; C669.1@142.75,63.65 v1(143.75,63.65) ; C665.2@142.75,84.85 143.65,84.85 143.875,84.625 v1(143.875,84.25) ; v1(149.5,64.25) 150.35,64.25 ; C670.1@150.35,63.25 150.35,64.25 ; C672.2@150.35,73.25 v1(151.5,73.25) ; C674.2@150.35,81.25 v1(151.5,81.25) ; v1(151.375,65.25) C671.2@150.35,65.25 150.35,64.25 ; v1(154.125,75.75) 154.125,76.5 154.375,76.75 C673.2@155.15,76.75
VDDA: C660.2 C663.1 C676.2 C678.1 CN4.5 CN104.5 CN204.5 CN304.5 D711.2 D712.2 D713.2 D721.2 D722.2 D731.2 D732.2 D741.2 D742.2 D812.2 D813.2 D912.2 IC600.36 IC600.54 J827.1 L654.2 | length 754
  TOP w0.25: D912.2@43.15,65.3 v1(45.718,65.3) ; v1(45.718,54.75) 50.875,54.75 ; D742.2@51.05,55.6 51.05,55 51.087,54.962 ; D741.2@65.55,55.6 v1(65.55,54.75) 51.3,54.75 ; v1(93.533,55.092) 94.041,55.6 D732.2@94.55,55.6 95.025,55.6 95.625,55 v1(103.25,55) 104.75,55 105,54.75 108.675,54.75 109.05,55.125 D731.2@109.05,55.6 ; D813.2@94.9,65.3 94.9,63.475 95.125,63.25 v1(103.25,63.25) ; v1(111.25,79) 111.25,78.25 v1(112.5,77) ; v1(125.9,80) 126.15,80.25 IC600.54@127.2,80.25 v1(131.875,80.25) 131.85,80.275 v1(131.85,84.25) 133.25,85.65 IC600.36@133.25,86.8 ; D722.2@193.05,54.85 193.525,54.85 194,54.375 200.75,54.375 v1(201,54.125) 206.425,54.125 206.8,54.5 D721.2@206.8,55.1 ; v1(207.65,62.875) D812.2@207.65,64.3 ; D712.2@235.05,56.1 235.05,55.5 235.3,55.25 v1(239.25,55.25) 249.8,55.25 250.05,55.5 D711.2@250.05,56.1 ; D713.2@235.9,65.8 235.9,63.975 236.125,63.75 v1(239.25,63.75) ; 50.875,54.75 51.087,54.962 ; 50.875,54.75 51.3,54.75 ; 51.087,54.962 51.3,54.75
  TOP w0.5: C663.1@123,102.5 123,100.375 123.375,100 v1(124.125,100)
  Mid-Layer 1 w0.25: v1(65.55,54.75) 69.25,58.45 78.547,58.45 82.357,54.64 93.081,54.64 v1(93.533,55.092)
  Mid-Layer 1 w1: v2(45.718,97.947) 85.758,97.947 87.31,96.395 120.521,96.395 v1(124.125,100) 127.041,100 128.946,98.095 198.034,98.095 201.928,94.201 225.296,94.201 v2(230.503,88.994) ; CN304.5@76,138 76,139.75 76.5,140.25 127.5,140.25 ; CN204.5@128,138 128,139.75 ; CN104.5@196,138 196,139.75 ; CN4.5@248,138 248,139.75 247.5,140.25 196.5,140.25 ; 127.5,140.25 128.5,140.25 ; 127.5,140.25 128,139.75 ; 128,139.75 128.5,140.25 ; 128.5,140.25 139.75,140.25 140.25,139.75 140.25,138 ccw(c145,138) 149.75,138 149.75,139.75 150.25,140.25 195.5,140.25 ; 195.5,140.25 196,139.75 ; 195.5,140.25 196.5,140.25 ; 196,139.75 196.5,140.25
  Mid-Layer 2 w0.25: v1(201,54.125) 201,55.847 202.968,57.815 215.771,57.815 216.697,58.742 233.83,58.742 237.322,55.25 v1(239.25,55.25)
  Mid-Layer 2 w1: v1(125.9,80) 123.5,80 122.75,80.75 122.75,93 124.125,94.375 v1(124.125,100) 124.125,100.5 128,104.375 CN204.5@128,138 ; v2(230.503,88.994) 230.503,75.976 239.25,67.229 v1(239.25,63.75)
  BOTTOM w0.25: v1(45.718,54.75) v1(45.718,65.3) ; v1(103.25,55) v1(103.25,63.25) ; v1(111.25,79) J827.1@112.375,79 ; v1(112.5,77) 115.25,77 117.625,74.625 125.5,74.625 125.9,75.025 v1(125.9,80) C678.1@125.9,81.25 ; C676.2@131.85,83.25 v1(131.85,84.25) ; v1(201,54.125) 201,56.25 207.625,62.875 v1(207.65,62.875) ; v1(239.25,55.25) v1(239.25,63.75)
  BOTTOM w0.5: C660.2@123.1,100 v1(124.125,100) L654.2@125.5,100
  BOTTOM w1: v1(45.718,65.3) v2(45.718,97.947)
VDDIO: C620.1 C621.1 C658.2 C661.2 C664.1 C680.2 C681.2 C682.2 C683.2 C684.2 C685.1 C686.1 C687.1 C688.1 C689.1 C690.1 C691.1 C692.1 C693.1 C694.1 C695.2 C696.2 C697.2 C698.2 C699.2 C700.2 CN1.1 CN101.1 CN201.1 CN301.1 IC600.3 IC600.11 IC600.15 IC600.20 IC600.26 IC600.62 IC600.68 IC600.75 IC600.82 IC600.88 IC600.91 IC600.99 IC600.106 IC600.114 IC600.116 IC600.119 IC600.127 IC600.138 IC600.147 IC600.152 IC600.159 IC600.168 IC620.3 IC620.5 IC621.5 L652.2 R500.2 R502.2 R631.1 R632.2 R633.2 R655.1 R656.2 R657.2 R658.2 | length 692.3
  TOP w0.25: v1(124.25,69.625) 124.375,69.625 124.5,69.75 IC600.75@127.2,69.75 ; IC600.88@127.2,63.25 128.25,63.25 v1(128.5,63.5) ; IC600.82@127.2,66.25 v1(128.5,66.25) ; IC600.68@127.2,73.25 v1(128.625,73.25) ; IC600.62@127.2,76.25 128.375,76.25 128.625,76 v1(128.625,75.25) ; v1(130.25,59.875) IC600.91@130.25,61.2 ; IC600.99@134.25,61.2 134.25,62.5 135.375,63.625 135.475,63.625 v1(135.5,63.65) ; v1(137.725,63.65) 137.75,63.625 IC600.106@137.75,61.2 ; v1(137.75,84.85) 137.75,84.875 138.25,85.375 IC600.26@138.25,86.8 ; IC600.20@141.25,86.8 141.25,85.375 141.75,84.875 v1(141.75,84.85) ; IC600.114@141.75,61.2 v1(141.75,63.65) 142.75,62.65 IC600.116@142.75,61.2 ; IC600.15@143.75,86.8 v1(143.75,91) 144.5,91 144.75,90.75 C682.2@144.75,90.15 ; IC600.119@144.25,61.2 144.25,60.25 144.625,59.875 v1(146.125,59.875) ; v1(145.75,85.5) IC600.11@145.75,86.8 ; v1(148,59.875) 148.25,60.125 IC600.127@148.25,61.2 ; IC600.3@149.75,86.8 149.75,87.75 150,88 151.875,88 v2(152.75,88.875) ; v1(151.375,76.125) 151.5,76.25 IC600.159@152.8,76.25 ; IC600.138@152.8,65.75 v1(154.125,65.75) ; IC600.147@152.8,70.25 154.65,70.25 C697.2@155.15,70.75 ; IC600.152@152.8,72.75 C698.2@155.15,72.75 ; IC600.168@152.8,80.75 C700.2@155.15,80.75
  TOP w0.5: v1(132.5,40) IC621.5@132.5,41.15 132.5,41.875 132.875,42.25 134.15,42.25 134.75,41.65 C621.1@135.5,41.65 136.25,41.65 136.5,41.9 136.5,46.6 136.75,46.85 R632.2@137.5,46.85 138.25,46.85 138.5,46.6 138.5,46.25 138.75,46 140.25,46 ; IC620.5@140.5,47.35 140.5,46.25 ; C620.1@143.5,45.15 142.625,45.15 142.125,44.65 IC620.3@141.45,44.65 141.45,45.75 141.2,46 140.75,46 ; v2(152.75,88.875) C680.2@152.75,90.15 ; v1(154.125,65.75) C696.2@155.15,65.75 ; C697.2@155.15,70.75 C698.2@155.15,72.75 R655.1@155.15,74.75 v1(155.15,75.75) ; C700.2@155.15,80.75 v1(155.15,81.75) ; 140.25,46 140.5,46.25 ; 140.25,46 140.75,46 ; 140.5,46.25 140.75,46
  TOP w1: C664.1@106.5,102.5 v2(109.75,102.5)
  Mid-Layer 1 w1: v2(48,102.5) v2(100,102.5) v2(109.75,102.5) 126.125,102.5 126.75,103.125 151.5,103.125 v2(153.75,100.875) ; v1(128.5,66.25) 131.65,66.25 134.25,63.65 v1(135.5,63.65) v1(137.725,63.65) v1(141.75,63.65) ; v1(137.75,84.85) v1(141.75,84.85) 141.75,84.875 143.5,86.625 145.25,86.625 145.75,86.125 v1(145.75,85.5) ; v1(143.75,91) 147.875,91 150,88.875 v2(152.75,88.875) ; v1(151.375,76.125) 152.25,76.125 152.875,76.75 154.875,76.75 155.15,76.475 v1(155.15,75.75) 158.15,78.75 v2(164.75,78.75) v2(201,78.75) ; v2(201,90.35) 201.85,89.5 218.15,89.5 v2(219,90.35)
  Mid-Layer 2 w0.5: v1(124.25,69.625) 125,69.625 125.125,69.75 127.25,69.75 ; v1(128.5,66.25) 127.75,66.25 127.5,66.5 127.5,69.5 ; v1(128.625,75.25) v1(128.625,73.25) 127.5,72.125 127.5,70 ; 127.25,69.75 127.5,69.5 ; 127.25,69.75 127.5,70 ; 127.5,69.5 127.5,70
  Mid-Layer 2 w1: v2(48,102.5) CN301.1@48,137.75 ; v2(96.5,91.625) 96.5,99 v2(100,102.5) CN201.1@100,138 ; v1(128.5,66.25) v1(128.5,63.5) 130.25,61.75 v1(130.25,59.875) ; v1(132.5,40) 146.125,53.625 v1(146.125,59.875) ; v1(135.5,63.65) 135.5,65.75 135.75,66 v1(135.75,75.25) ; v1(143.75,91) 145.75,89 v1(145.75,85.5) ; v1(150.35,68.25) 150.35,70.15 148.875,71.625 148.875,73.625 v1(151.375,76.125) ; v2(153.75,100.875) 153.75,91.875 152.75,90.875 v2(152.75,88.875) 155.15,86.475 v1(155.15,81.75) v1(155.15,75.75) 155.15,73.025 154.125,72 v1(154.125,65.75) ; v2(164.75,78.75) 164.25,79.25 164.25,87.875 165.375,89 v1(165.375,90.25) 165.375,133 167,134.625 CN101.1@167,138 ; v2(201,78.75) v2(201,90.35) ; v2(219,90.35) 219,135.375 220,136.375 CN1.1@220,138
  BOTTOM w0.25: v1(128.5,63.5) 128.75,63.25 C689.1@129.65,63.25 ; v1(145.75,85.5) 145.75,88.375 146.75,89.375 C681.2@146.75,90.15
  BOTTOM w0.5: R658.2@92.6,89.25 R657.2@96.9,89.25 ; v2(96.5,91.625) 96.5,90.25 96.9,89.85 R657.2@96.9,89.25 ; R656.2@96.9,79.25 R657.2@96.9,89.25 ; C661.2@107.475,99 107.475,100.25 ; C658.2@107.475,101.5 107.475,100.25 ; v2(109.75,102.5) L652.2@109.75,100 108.625,100 108.375,100.25 107.475,100.25 ; v1(124.25,69.625) C687.1@125.275,69.625 ; v1(128.5,66.25) 129.375,66.25 129.65,66.525 C688.1@129.65,67.25 ; v1(128.625,73.25) C686.1@129.65,73.25 ; v1(128.625,75.25) C685.1@129.65,75.25 ; C690.1@129.65,61.25 129.65,60.475 v1(130.25,59.875) ; v1(132.5,40) 133.5,41 R633.2@133.5,41.65 ; C691.1@134.25,63.65 v1(135.5,63.65) C692.1@136.75,63.65 v1(137.725,63.65) ; C684.2@136.75,84.85 v1(137.75,84.85) ; C683.2@140.75,84.85 v1(141.75,84.85) ; v1(141.75,63.65) C694.1@140.75,63.65 C693.1@138.75,63.65 v1(137.725,63.65) ; v1(150.35,68.25) R631.1@150.35,67.25 150.35,66.75 151.1,66 151.75,66 152.125,65.625 152.125,61.5 151.875,61.25 C695.2@150.35,61.25 150.35,60.125 150.1,59.875 v1(148,59.875) v1(146.125,59.875) 138,59.875 137.725,60.15 v1(137.725,63.65) ; C699.2@150.35,75.25 150.35,76 150.6,76.25 151.25,76.25 v1(151.375,76.125) ; R500.2@164.35,90.25 v1(165.375,90.25) ; R502.2@199,90.35 v2(201,90.35)
VDDOSC: C659.2 C662.1 C677.1 C679.1 IC600.120 IC600.125 L653.2 | length 48.7
  TOP w0.25: IC600.120@144.75,61.2 v1(144.75,62.625) ; v1(147.125,62.625) 147.125,62.25 147.25,62.125 IC600.125@147.25,61.2
  TOP w1: C662.1@124,47 124,44.5 v1(125,43.5)
  Mid-Layer 1 w1: v1(144.75,62.625) v1(147.125,62.625)
  Mid-Layer 2 w1: v1(125,43.5) 134,43.5 144.75,54.25 v1(144.75,62.625) v1(147.125,62.625)
  BOTTOM w0.5: C659.2@125,42.35 v1(125,43.5) L653.2@125,44.75 ; v1(144.75,62.625) C677.1@144.75,63.65 ; C679.1@146.75,63.65 146.75,63 v1(147.125,62.625)
VP_3R3V_SYS: C654.2 C655.2 C656.2 C675.1 IC600.72 J805.2 L652.1 L653.1 L654.1 R514.1 R515.1 R524.2 R525.2 R534.2 R535.2 R544.1 R545.1 R565.2 R569.2 R575.2 R579.2 R585.2 R589.2 R595.2 R599.2 | length 270.8
  TOP w0.25: v1(123.15,71.125) 123.275,71.25 IC600.72@127.2,71.25
  TOP w0.5: v1(136,56.125) R534.2@136,57.15
  Mid-Layer 1 w1: v1(123,43.5) 123,39.375 123.5,38.875 135.25,38.875 v1(137.5,41.125) ; v1(123.15,71.125) 123.275,71.25 v1(134.5,71.25) 136.375,69.375 v1(145.75,69.375) v2(162,69.375) ; v2(126.875,98) 126.875,97.1 127.375,96.6 v1(134.975,96.6) ; v1(128.6,57.15) 128.6,55.275 129,54.875 134.75,54.875 v1(136,56.125) ; v1(155.15,64.75) 156.75,64.75 156.875,64.875 157.875,64.875 158,64.75 v2(162,64.75) ; v2(162,81.625) v2(170.5,81.625) v2(180,81.625) v2(190,81.625) v2(199.5,81.625)
  Mid-Layer 2 w1: v1(123,43.5) 122.5,44 122.5,54.375 124.5,56.375 ; v1(123.15,71.125) 123.15,69.225 124.5,67.875 124.5,57.375 ; v1(128.6,57.15) 128.325,56.875 125,56.875 ; v1(134.5,71.25) 134.5,76.875 v1(135.75,78.125) 134.75,79.125 134.75,85.5 137.375,88.125 137.375,90.375 134.975,92.775 v1(134.975,96.6) ; v2(162,64.75) v2(162,69.375) v2(162,81.625) ; 124.5,56.375 124.5,57.375 ; 124.5,56.375 125,56.875 ; 124.5,57.375 125,56.875
  BOTTOM w0.5: C654.2@107.475,96.5 109.75,96.5 ; L652.1@109.75,98 109.75,96.5 ; C655.2@123,42.35 v1(123,43.5) L653.1@123,44.75 ; C656.2@123.1,98 L654.1@125.5,98 ; v1(123.15,71.125) 123.65,71.125 C675.1@124.275,71.75 ; v2(126.875,98) L654.1@125.5,98 ; v1(128.6,57.15) R524.2@130.25,57.15 ; v1(134.975,96.6) R569.2@136,96.6 ; v1(135.75,78.125) 136,78.375 R515.1@136,79.15 R514.1@138,79.15 ; v1(136,56.125) 136.25,56.375 R535.2@136.25,57.15 ; v1(137.5,41.125) J805.2@137.5,42.125 ; v1(145.75,69.375) 145.775,69.35 R525.2@146.75,69.35 147.525,69.35 147.625,69.25 R545.1@148.65,69.25 ; v1(155.15,64.75) R544.1@155.15,65.75 ; v2(162,81.625) 162,84.1 162.25,84.35 R599.2@164.5,84.35 ; R595.2@170.5,80.35 v2(170.5,81.625) 170.5,84.1 170.75,84.35 R589.2@174,84.35 ; R585.2@180,80.35 v2(180,81.625) 180,84.1 180.25,84.35 R579.2@184,84.35 ; R575.2@190,80.35 v2(190,81.625) ; R565.2@199.5,80.35 v2(199.5,81.625) ; 109.75,96.5 118.875,96.5 119.125,96.75 125.25,96.75 125.5,97 L654.1@125.5,98
VP_5R0: C635.2 C636.2 C637.2 C648.2 CN1.2 CN101.2 CN201.2 CN301.2 IC106.5 IC807.5 IC808.5 IC809.5 J803.2 J826.1 R516.2 R517.2 R518.2 R519.2 R526.2 R527.2 R528.2 R529.2 R536.2 R537.2 R538.2 R539.2 R546.2 R547.2 R548.2 R549.2 | length 405.2
  TOP w0.5: J826.1@157,42.125 157.125,42.25 v2(157.125,43.625) J803.2@157.125,45.25 ; C636.2@169.1,90.25 169.1,89.5 v1(169.35,89.25) IC808.5@169.35,88.4 ; C637.2@174.1,90.25 174.1,89.5 v1(174.35,89.25) IC809.5@174.35,88.4 ; C635.2@179.1,90.25 179.1,89.5 v1(179.35,89.25) IC807.5@179.35,88.4 ; C648.2@184.1,90.25 184.1,89.5 v1(184.35,89.25) IC106.5@184.35,88.4
  Mid-Layer 1 w1: CN301.2@46,137.75 46,136.5 46.5,136 97.5,136 ; CN201.2@98,138 98,136.5 ; 139.209,136.006 ccw(c145,138) 139.211,136 ; 150.791,136.006 cw(c145,138) 150.789,136 ; v1(164.625,65) v1(171.375,65) v1(174.625,65) v1(181.375,65) v1(184.625,65) v1(191.375,65) v1(194.125,65) v1(201,65) ; CN101.2@165,138 165,136.5 ; v1(165.125,71.25) v1(171.875,71.25) v1(174.625,71.25) v1(181.375,71.25) v1(184.625,71.25) v1(191.375,71.25) v1(194.125,71.25) v1(201,71.25) ; v1(169.35,89.25) v1(174.35,89.25) v1(179.35,89.25) v1(184.35,89.25) ; CN1.2@218,138 218,136.5 217.5,136 v2(169.35,136) 165.5,136 ; 97.5,136 98,136.5 ; 97.5,136 98.5,136 ; 98,136.5 98.5,136 ; 98.5,136 139.211,136 ; 139.211,136 ccw(c145,138) 150.789,136 ; 150.789,136 164.5,136 ; 164.5,136 165,136.5 ; 164.5,136 165.5,136 ; 165,136.5 165.5,136
  Mid-Layer 2 w1: v2(157.125,43.625) 157.125,52.75 165.375,61 165.375,64.25 v1(164.625,65) ; v1(169.35,89.25) v2(169.35,136) ; v1(179.35,89.25) 179.35,85.275 181.375,83.25 v1(181.375,71.25) ; v1(201,65) v1(201,71.25)
  BOTTOM w0.5: v1(164.625,65) 164.625,64.4 164.875,64.15 R549.2@165.5,64.15 ; v1(165.125,71.25) 165.125,70.65 165.375,70.4 R547.2@166,70.4 ; R548.2@170.5,65.85 171.125,65.85 171.375,65.6 v1(171.375,65) ; R546.2@171,72.1 171.625,72.1 171.875,71.85 v1(171.875,71.25) ; v1(174.625,65) 174.625,64.4 174.875,64.15 R539.2@175.5,64.15 ; v1(174.625,71.25) 174.625,70.65 174.875,70.4 R537.2@175.5,70.4 ; R538.2@180.5,65.85 181.125,65.85 181.375,65.6 v1(181.375,65) ; R536.2@180.5,72.1 181.125,72.1 181.375,71.85 v1(181.375,71.25) ; v1(184.625,65) 184.625,64.4 184.875,64.15 R529.2@185.5,64.15 ; v1(184.625,71.25) 184.625,70.65 184.875,70.4 R527.2@185.5,70.4 ; R528.2@190.5,65.85 191.125,65.85 191.375,65.6 v1(191.375,65) ; R526.2@190.5,72.1 191.125,72.1 191.375,71.85 v1(191.375,71.25) ; v1(194.125,65) 194.125,64.4 194.375,64.15 R519.2@195,64.15 ; v1(194.125,71.25) 194.125,70.65 194.375,70.4 R517.2@195,70.4 ; R518.2@200,65.85 200.775,65.85 201,65.625 v1(201,65) ; R516.2@200,72.1 200.65,72.1 201,71.75 v1(201,71.25)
